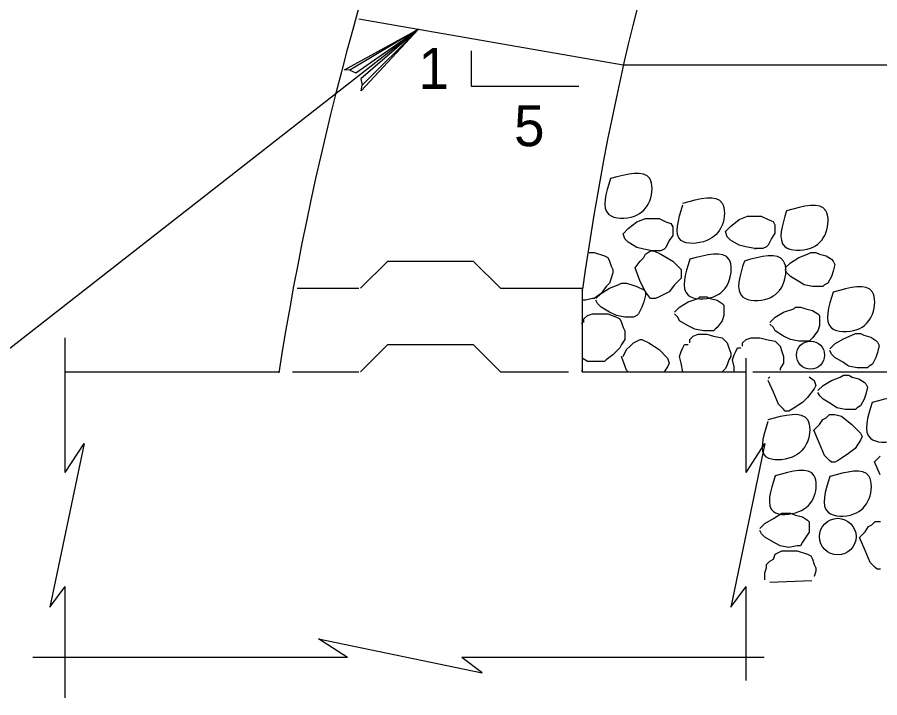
# Model space of a CAD drawing. Extents: x 639028 to 639883, y 298843 to 300031.
# Drawn here: x 639461 to 639524.2, y 299557.3 to 299607.2 of the extents above; entities that cross this region are included whole.
import ezdxf

# ---------------------------------------------------------------- set-up
doc = ezdxf.new("R2010")
doc.units = 0
doc.layers.add('2', color=7, linetype='Continuous')
doc.layers.add('52', color=7, linetype='Continuous')

msp = doc.modelspace()

# ---------------------------------------------------------------- linework, layer by layer
at = {"layer": '2'}
for p, q in [((639485.989, 299607.079), (639505.364, 299603.704)), ((639490.364, 299606.329), (639453.739, 299577.704)), ((639494.245, 299602.124), (639494.245, 299604.732)), ((639505.364, 299603.704), (639538.418, 299603.704)), ((639502.12, 299602.124), (639494.245, 299602.124)), ((639486.114, 299587.329), (639488.114, 299589.329)), ((639488.114, 299589.329), (639494.364, 299589.329)), ((639494.364, 299589.329), (639496.364, 299587.329)), ((639481.489, 299587.329), (639485.989, 299587.329)), ((639496.364, 299587.329), (639502.364, 299587.329)), ((639502.364, 299587.329), (639502.364, 299581.204)), ((639464.489, 299573.829), (639464.489, 299583.704)), ((639486.114, 299581.204), (639488.114, 299583.204)), ((639488.114, 299583.204), (639494.364, 299583.204)), ((639494.364, 299583.204), (639496.364, 299581.204)), ((639514.364, 299573.829), (639514.364, 299582.204)), ((639464.489, 299581.204), (639480.114, 299581.204)), ((639481.128, 299581.204), (639485.989, 299581.204)), ((639496.364, 299581.204), (639501.367, 299581.204)), ((639502.364, 299581.204), (639514.364, 299581.204)), ((639514.864, 299581.204), (639523.364, 299581.204)), ((639515.864, 299581.204), (639532.489, 299581.204)), ((639464.489, 299557.303), (639464.489, 299565.454)), ((639514.364, 299558.566), (639514.364, 299565.454)), ((639485.16, 299560.246), (639462.118, 299560.246)), ((639515.702, 299560.246), (639493.535, 299560.246))]:
    msp.add_line(p, q, dxfattribs=at)
for points in [[(639504.12, 299597.124), (639504.12, 299597.124)], [(639503.739, 299595.329), (639503.739, 299595.329)], [(639513.853, 299592.361), (639514.478, 299592.611)], [(639514.478, 299592.611), (639514.728, 299592.611)], [(639514.728, 299592.611), (639515.103, 299592.611)], [(639515.103, 299592.611), (639515.478, 299592.611)], [(639515.478, 299592.611), (639515.978, 299592.361)], [(639505.739, 299591.704), (639506.364, 299592.204)], [(639506.364, 299592.204), (639506.989, 299592.454)], [(639506.989, 299592.454), (639507.239, 299592.454)], [(639507.239, 299592.454), (639507.614, 299592.454)], [(639507.614, 299592.454), (639507.989, 299592.454)], [(639507.989, 299592.454), (639508.489, 299592.204)], [(639508.489, 299592.204), (639508.864, 299592.079)], [(639508.864, 299592.079), (639508.989, 299591.829)], [(639513.228, 299591.861), (639513.853, 299592.361)], [(639515.978, 299592.361), (639516.353, 299592.236)], [(639516.353, 299592.236), (639516.478, 299591.986)], [(639516.478, 299591.986), (639516.478, 299591.861)], [(639505.364, 299591.329), (639505.739, 299591.704)], [(639505.489, 299590.954), (639505.364, 299591.329)], [(639508.989, 299591.829), (639508.989, 299591.704)], [(639508.989, 299591.704), (639508.989, 299591.204)], [(639512.853, 299591.486), (639513.228, 299591.861)], [(639512.978, 299591.111), (639512.853, 299591.486)], [(639516.478, 299591.361), (639516.228, 299590.986)], [(639516.478, 299591.861), (639516.478, 299591.361)], [(639505.739, 299590.704), (639505.489, 299590.954)], [(639506.364, 299590.329), (639505.739, 299590.704)], [(639508.739, 299590.829), (639508.489, 299590.329)], [(639508.989, 299591.204), (639508.739, 299590.829)], [(639513.228, 299590.861), (639512.978, 299591.111)], [(639513.853, 299590.486), (639513.228, 299590.861)], [(639516.228, 299590.986), (639515.978, 299590.486)], [(639506.864, 299590.204), (639506.364, 299590.329)], [(639507.489, 299590.079), (639506.864, 299590.204)], [(639506.989, 299589.829), (639507.364, 299590.079)], [(639507.364, 299590.079), (639507.489, 299590.079)], [(639507.489, 299590.079), (639507.614, 299590.079)], [(639508.114, 299590.079), (639507.489, 299590.079)], [(639507.614, 299590.079), (639508.114, 299589.829)], [(639508.364, 299590.204), (639508.114, 299590.079)], [(639508.489, 299590.329), (639508.364, 299590.204)], [(639514.353, 299590.361), (639513.853, 299590.486)], [(639514.978, 299590.236), (639514.353, 299590.361)], [(639514.978, 299590.236), (639515.103, 299590.236)], [(639515.603, 299590.236), (639514.978, 299590.236)], [(639515.853, 299590.361), (639515.603, 299590.236)], [(639515.978, 299590.486), (639515.853, 299590.361)], [(639502.864, 299589.954), (639503.239, 299589.954)], [(639503.239, 299589.954), (639503.989, 299589.704)], [(639503.989, 299589.704), (639504.239, 299589.579)], [(639504.239, 299589.579), (639504.364, 299589.329)], [(639506.614, 299589.329), (639506.864, 299589.579)], [(639506.864, 299589.579), (639506.989, 299589.829)], [(639508.114, 299589.829), (639508.989, 299589.329)], [(639517.614, 299589.204), (639518.239, 299589.579)], [(639518.239, 299589.579), (639518.864, 299589.829)], [(639518.864, 299589.829), (639519.114, 299589.954)], [(639519.114, 299589.954), (639519.489, 299589.954)], [(639519.489, 299589.954), (639519.739, 299589.829)], [(639519.739, 299589.829), (639520.239, 299589.704)], [(639520.239, 299589.704), (639520.614, 299589.454)], [(639520.614, 299589.454), (639520.739, 299589.329)], [(639504.364, 299589.329), (639504.489, 299588.954)], [(639504.489, 299588.954), (639504.614, 299588.704)], [(639506.239, 299588.829), (639506.614, 299589.329)], [(639506.614, 299587.829), (639506.239, 299588.829)], [(639508.989, 299589.329), (639509.614, 299588.704)], [(639517.239, 299588.829), (639517.614, 299589.204)], [(639520.739, 299589.329), (639520.864, 299589.079)], [(639520.864, 299589.079), (639520.739, 299588.579)], [(639504.489, 299588.079), (639504.364, 299587.704)], [(639504.614, 299588.454), (639504.489, 299588.079)], [(639504.614, 299588.704), (639504.614, 299588.454)], [(639509.614, 299588.079), (639509.114, 299587.579)], [(639509.614, 299588.704), (639509.614, 299588.454)], [(639509.614, 299588.454), (639509.614, 299588.079)], [(639517.364, 299588.454), (639517.239, 299588.704)], [(639517.614, 299588.204), (639517.364, 299588.454)], [(639518.239, 299587.829), (639517.614, 299588.204)], [(639520.614, 299588.204), (639520.364, 299587.704)], [(639520.739, 299588.579), (639520.614, 299588.204)], [(639504.114, 299587.454), (639503.739, 299586.954)], [(639504.364, 299587.704), (639504.114, 299587.454)], [(639504.364, 299587.329), (639504.989, 299587.579)], [(639504.989, 299587.579), (639505.239, 299587.704)], [(639505.239, 299587.704), (639505.614, 299587.704)], [(639505.614, 299587.704), (639505.989, 299587.579)], [(639505.989, 299587.579), (639506.364, 299587.454)], [(639506.364, 299587.454), (639506.864, 299587.204)], [(639506.989, 299587.079), (639506.614, 299587.829)], [(639509.114, 299587.579), (639508.739, 299587.079)], [(639518.614, 299587.579), (639518.239, 299587.829)], [(639519.239, 299587.454), (639518.614, 299587.579)], [(639519.989, 299587.454), (639519.239, 299587.454)], [(639520.114, 299587.579), (639519.989, 299587.454)], [(639520.364, 299587.704), (639520.114, 299587.579)], [(639503.739, 299586.954), (639503.239, 299586.579)], [(639503.364, 299586.579), (639503.739, 299586.954)], [(639503.739, 299586.954), (639504.364, 299587.329)], [(639506.864, 299587.204), (639506.989, 299587.079)], [(639506.989, 299586.829), (639506.864, 299586.329)], [(639507.364, 299586.579), (639506.989, 299587.079)], [(639506.989, 299587.079), (639506.989, 299586.829)], [(639508.739, 299587.079), (639507.989, 299586.704)], [(639502.614, 299586.454), (639502.364, 299586.454)], [(639503.114, 299586.579), (639502.614, 299586.454)], [(639503.239, 299586.579), (639503.114, 299586.579)], [(639503.489, 299586.204), (639503.364, 299586.454)], [(639503.739, 299585.954), (639503.489, 299586.204)], [(639506.864, 299586.329), (639506.739, 299585.954)], [(639507.489, 299586.579), (639507.364, 299586.579)], [(639507.739, 299586.579), (639507.489, 299586.579)], [(639507.989, 299586.704), (639507.739, 299586.579)], [(639509.489, 299585.954), (639510.114, 299586.329)], [(639510.114, 299586.329), (639510.864, 299586.579)], [(639510.864, 299586.579), (639510.989, 299586.704)], [(639510.989, 299586.704), (639511.489, 299586.704)], [(639511.489, 299586.704), (639511.739, 299586.579)], [(639511.739, 299586.579), (639512.239, 299586.454)], [(639512.239, 299586.454), (639512.614, 299586.204)], [(639512.614, 299586.204), (639512.739, 299586.079)], [(639504.364, 299585.579), (639503.739, 299585.954)], [(639504.864, 299585.329), (639504.364, 299585.579)], [(639506.739, 299585.954), (639506.489, 299585.454)], [(639509.114, 299585.579), (639509.489, 299585.954)], [(639512.739, 299586.079), (639512.739, 299585.829)], [(639512.739, 299585.829), (639512.739, 299585.329)], [(639516.489, 299585.204), (639517.114, 299585.579)], [(639517.114, 299585.579), (639517.864, 299585.829)], [(639517.864, 299585.829), (639517.989, 299585.954)], [(639517.989, 299585.954), (639518.364, 299585.954)], [(639518.364, 299585.954), (639518.739, 299585.829)], [(639518.739, 299585.829), (639519.239, 299585.704)], [(639519.239, 299585.704), (639519.614, 299585.454)], [(639502.489, 299585.079), (639502.739, 299585.329)], [(639502.489, 299584.829), (639502.489, 299585.079)], [(639502.739, 299585.329), (639503.114, 299585.454)], [(639503.114, 299585.454), (639503.739, 299585.454)], [(639503.739, 299585.454), (639504.239, 299585.454)], [(639504.239, 299585.454), (639504.864, 299585.204)], [(639505.489, 299585.204), (639504.864, 299585.329)], [(639504.864, 299585.204), (639505.114, 299585.079)], [(639505.114, 299585.079), (639505.239, 299584.829)], [(639506.114, 299585.204), (639505.489, 299585.204)], [(639506.364, 299585.329), (639506.114, 299585.204)], [(639506.489, 299585.454), (639506.364, 299585.329)], [(639509.364, 299585.204), (639509.114, 299585.454)], [(639509.489, 299584.954), (639509.364, 299585.204)], [(639510.114, 299584.579), (639509.489, 299584.954)], [(639512.614, 299584.954), (639512.239, 299584.454)], [(639512.739, 299585.329), (639512.614, 299584.954)], [(639516.114, 299584.829), (639516.489, 299585.204)], [(639519.614, 299585.454), (639519.739, 299585.329)], [(639519.739, 299585.329), (639519.739, 299585.079)], [(639519.739, 299585.079), (639519.739, 299584.579)], [(639502.364, 299584.704), (639502.364, 299584.829)], [(639505.239, 299584.829), (639505.364, 299584.454)], [(639505.364, 299584.454), (639505.489, 299584.204)], [(639510.614, 299584.329), (639510.114, 299584.579)], [(639511.239, 299584.204), (639510.614, 299584.329)], [(639512.114, 299584.329), (639511.989, 299584.204)], [(639512.239, 299584.454), (639512.114, 299584.329)], [(639516.364, 299584.454), (639516.114, 299584.704)], [(639516.489, 299584.204), (639516.364, 299584.454)], [(639519.739, 299584.579), (639519.614, 299584.204)], [(639505.489, 299584.204), (639505.489, 299583.954)], [(639505.489, 299583.954), (639505.489, 299583.579)], [(639510.239, 299583.579), (639510.489, 299583.829)], [(639510.489, 299583.829), (639510.864, 299583.954)], [(639510.864, 299583.954), (639511.489, 299583.954)], [(639511.989, 299584.204), (639511.239, 299584.204)], [(639511.489, 299583.954), (639511.989, 299583.829)], [(639511.989, 299583.829), (639512.614, 299583.704)], [(639512.614, 299583.704), (639512.864, 299583.454)], [(639514.364, 299583.579), (639514.739, 299583.704)], [(639514.739, 299583.704), (639515.364, 299583.704)], [(639515.364, 299583.704), (639515.864, 299583.579)], [(639517.114, 299583.829), (639516.489, 299584.204)], [(639517.614, 299583.579), (639517.114, 299583.829)], [(639519.239, 299583.704), (639519.114, 299583.579)], [(639519.614, 299584.204), (639519.239, 299583.704)], [(639521.501, 299583.63), (639522.126, 299583.88)], [(639522.126, 299583.88), (639522.376, 299584.005)], [(639522.376, 299584.005), (639522.751, 299584.005)], [(639522.751, 299584.005), (639523.001, 299583.88)], [(639523.001, 299583.88), (639523.501, 299583.755)], [(639523.501, 299583.755), (639523.876, 299583.505)], [(639505.239, 299583.204), (639505.114, 299582.954)], [(639505.489, 299583.579), (639505.239, 299583.204)], [(639505.614, 299582.829), (639505.864, 299583.079)], [(639505.864, 299583.079), (639506.114, 299583.329)], [(639506.114, 299583.329), (639506.364, 299583.454)], [(639506.364, 299583.454), (639506.614, 299583.579)], [(639506.614, 299583.579), (639506.739, 299583.579)], [(639506.739, 299583.579), (639507.239, 299583.329)], [(639507.239, 299583.329), (639507.989, 299582.829)], [(639509.739, 299582.954), (639509.864, 299583.204)], [(639509.864, 299583.204), (639510.114, 299583.204)], [(639510.239, 299583.329), (639510.239, 299583.579)], [(639512.864, 299583.454), (639512.989, 299583.329)], [(639512.989, 299583.329), (639513.114, 299582.954)], [(639514.114, 299583.329), (639514.364, 299583.579)], [(639514.114, 299583.079), (639514.114, 299583.329)], [(639515.864, 299583.579), (639516.489, 299583.454)], [(639516.489, 299583.454), (639516.739, 299583.204)], [(639516.739, 299583.204), (639516.864, 299583.079)], [(639516.864, 299583.079), (639516.989, 299582.704)], [(639518.239, 299583.454), (639517.614, 299583.579)], [(639518.989, 299583.454), (639518.239, 299583.454)], [(639519.114, 299583.579), (639518.989, 299583.454)], [(639520.501, 299582.88), (639520.876, 299583.255)], [(639520.876, 299583.255), (639521.501, 299583.63)], [(639523.876, 299583.505), (639524.001, 299583.38)], [(639524.001, 299583.38), (639524.126, 299583.13)], [(639524.126, 299583.13), (639524.001, 299582.63)], [(639504.614, 299582.454), (639504.114, 299582.079)], [(639505.114, 299582.954), (639504.614, 299582.454)], [(639505.364, 299582.329), (639505.614, 299582.829)], [(639507.989, 299582.829), (639508.614, 299582.204)], [(639509.489, 299582.329), (639509.614, 299582.704)], [(639509.614, 299582.704), (639509.739, 299582.954)], [(639513.114, 299582.954), (639513.239, 299582.579)], [(639513.239, 299582.579), (639513.239, 299582.329)], [(639513.364, 299582.079), (639513.489, 299582.454)], [(639513.489, 299582.454), (639513.614, 299582.704)], [(639513.614, 299582.704), (639513.739, 299582.954)], [(639513.739, 299582.954), (639513.989, 299582.954)], [(639516.989, 299582.704), (639517.114, 299582.329)], [(639520.626, 299582.505), (639520.501, 299582.755)], [(639520.876, 299582.255), (639520.626, 299582.505)], [(639524.001, 299582.63), (639523.876, 299582.255)], [(639502.739, 299581.954), (639502.364, 299582.204), (639502.364, 299582.204)], [(639503.239, 299581.954), (639502.739, 299581.954)], [(639503.614, 299581.954), (639503.239, 299581.954)], [(639503.989, 299581.954), (639503.614, 299581.954)], [(639504.114, 299582.079), (639503.989, 299581.954)], [(639505.614, 299581.329), (639505.239, 299582.329)], [(639508.614, 299582.204), (639508.739, 299581.829)], [(639508.739, 299581.829), (639508.614, 299581.579)], [(639509.614, 299581.829), (639509.489, 299582.329)], [(639509.739, 299581.204), (639509.614, 299581.829)], [(639513.114, 299582.079), (639512.989, 299581.704)], [(639513.239, 299582.329), (639513.114, 299582.079)], [(639513.489, 299581.579), (639513.364, 299582.079)], [(639517.114, 299581.829), (639516.864, 299581.454)], [(639517.114, 299582.329), (639517.114, 299582.079)], [(639517.114, 299582.079), (639517.114, 299581.829)], [(639521.501, 299581.88), (639520.876, 299582.255)], [(639521.876, 299581.63), (639521.501, 299581.88)], [(639523.876, 299582.255), (639523.626, 299581.755)], [(639502.364, 299581.204), (639502.364, 299581.329)], [(639505.739, 299581.204), (639505.614, 299581.329)], [(639505.614, 299581.204), (639505.614, 299581.204)], [(639508.614, 299581.579), (639508.364, 299581.204)], [(639512.864, 299581.454), (639512.614, 299581.204)], [(639512.989, 299581.704), (639512.864, 299581.454)], [(639513.489, 299581.204), (639513.489, 299581.579)], [(639516.864, 299581.454), (639516.864, 299581.329)], [(639522.501, 299581.505), (639521.876, 299581.63)], [(639523.251, 299581.505), (639522.501, 299581.505)], [(639523.376, 299581.63), (639523.251, 299581.505)], [(639523.626, 299581.755), (639523.376, 299581.63)], [(639515.989, 299580.704), (639516.114, 299580.829)], [(639516.364, 299579.704), (639515.989, 299580.579)], [(639518.989, 299580.829), (639519.364, 299580.579)], [(639519.364, 299580.579), (639519.489, 299580.204)], [(639520.009, 299580.198), (639520.634, 299580.573)], [(639520.634, 299580.573), (639521.259, 299580.823)], [(639521.259, 299580.823), (639521.509, 299580.948)], [(639521.509, 299580.948), (639521.884, 299580.948)], [(639521.884, 299580.948), (639522.134, 299580.823)], [(639522.134, 299580.823), (639522.634, 299580.698)], [(639522.634, 299580.698), (639523.009, 299580.448)], [(639519.364, 299579.954), (639518.864, 299579.329)], [(639519.489, 299580.204), (639519.364, 299579.954)], [(639519.634, 299579.823), (639520.009, 299580.198)], [(639523.009, 299580.448), (639523.134, 299580.323)], [(639523.134, 299580.323), (639523.259, 299580.073)], [(639523.259, 299580.073), (639523.134, 299579.573)], [(639516.739, 299578.829), (639516.364, 299579.704)], [(639518.864, 299579.329), (639518.489, 299578.954)], [(639519.759, 299579.448), (639519.634, 299579.698)], [(639520.009, 299579.198), (639519.759, 299579.448)], [(639523.134, 299579.573), (639523.009, 299579.198)], [(639517.114, 299578.454), (639516.739, 299578.829)], [(639518.489, 299578.954), (639517.739, 299578.454)], [(639520.634, 299578.823), (639520.009, 299579.198)], [(639521.009, 299578.573), (639520.634, 299578.823)], [(639522.759, 299578.698), (639522.509, 299578.573)], [(639523.009, 299579.198), (639522.759, 299578.698)], [(639517.239, 299578.329), (639517.114, 299578.454)], [(639517.489, 299578.329), (639517.239, 299578.329)], [(639517.739, 299578.454), (639517.489, 299578.329)], [(639520.239, 299577.829), (639520.489, 299578.079)], [(639520.489, 299578.079), (639520.614, 299578.079)], [(639520.614, 299578.079), (639520.864, 299578.079)], [(639520.864, 299578.079), (639521.364, 299577.954)], [(639521.634, 299578.448), (639521.009, 299578.573)], [(639522.384, 299578.448), (639521.634, 299578.448)], [(639522.509, 299578.573), (639522.384, 299578.448)], [(639519.739, 299577.329), (639519.989, 299577.704)], [(639519.989, 299577.704), (639520.239, 299577.829)], [(639521.364, 299577.954), (639522.114, 299577.329)], [(639519.327, 299576.917), (639519.739, 299577.329)], [(639519.739, 299575.954), (639519.327, 299576.917)], [(639522.114, 299577.329), (639522.739, 299576.704)], [(639522.739, 299576.704), (639522.864, 299576.454)], [(639522.739, 299576.204), (639522.364, 299575.579)], [(639522.864, 299576.454), (639522.739, 299576.204)], [(639464.489, 299573.829), (639465.864, 299575.954), (639463.364, 299563.954), (639464.489, 299565.454)], [(639514.364, 299573.829), (639515.739, 299575.954), (639513.239, 299563.954), (639514.364, 299565.454)], [(639520.114, 299575.079), (639519.739, 299575.954)], [(639522.364, 299575.579), (639521.864, 299575.204)], [(639520.489, 299574.704), (639520.114, 299575.079)], [(639521.864, 299575.204), (639521.114, 299574.704)], [(639523.781, 299574.608), (639524.193, 299575.02)], [(639520.614, 299574.579), (639520.489, 299574.704)], [(639520.864, 299574.579), (639520.614, 299574.579)], [(639521.114, 299574.704), (639520.864, 299574.579)], [(639524.193, 299573.645), (639523.781, 299574.608)], [(639515.739, 299570.079), (639516.364, 299570.454)], [(639516.364, 299570.454), (639516.989, 299570.829)], [(639516.989, 299570.829), (639517.239, 299570.829)], [(639517.239, 299570.829), (639517.614, 299570.829)], [(639517.614, 299570.829), (639517.989, 299570.704)], [(639517.989, 299570.704), (639518.489, 299570.579)], [(639518.489, 299570.579), (639518.864, 299570.329)], [(639515.364, 299569.704), (639515.739, 299570.079)], [(639518.864, 299570.329), (639518.989, 299570.204)], [(639518.989, 299570.204), (639518.989, 299569.954)], [(639518.989, 299569.954), (639518.989, 299569.454)], [(639523.085, 299569.479), (639523.335, 299569.854)], [(639523.335, 299569.854), (639523.585, 299569.979)], [(639523.585, 299569.979), (639523.835, 299570.229)], [(639523.835, 299570.229), (639523.96, 299570.229)], [(639523.96, 299570.229), (639524.21, 299570.229)], [(639515.489, 299569.329), (639515.364, 299569.579)], [(639515.739, 299569.079), (639515.489, 299569.329)], [(639518.989, 299569.454), (639518.739, 299569.079)], [(639522.673, 299569.066), (639523.085, 299569.479)], [(639516.364, 299568.704), (639515.739, 299569.079)], [(639516.864, 299568.454), (639516.364, 299568.704)], [(639518.489, 299568.704), (639518.364, 299568.454)], [(639518.739, 299569.079), (639518.489, 299568.704)], [(639522.364, 299568.829), (639522.364, 299568.829)], [(639523.085, 299568.104), (639522.673, 299569.066)], [(639516.489, 299567.829), (639516.739, 299567.954)], [(639516.739, 299567.954), (639516.989, 299568.079)], [(639517.489, 299568.329), (639516.864, 299568.454)], [(639516.989, 299568.079), (639517.614, 299568.079)], [(639518.114, 299568.454), (639517.489, 299568.329)], [(639517.614, 299568.079), (639518.114, 299568.079)], [(639518.364, 299568.454), (639518.114, 299568.454)], [(639518.114, 299568.079), (639518.864, 299567.829)], [(639523.46, 299567.229), (639523.085, 299568.104)], [(639515.864, 299567.079), (639516.114, 299567.329)], [(639516.114, 299567.329), (639516.364, 299567.454)], [(639516.364, 299567.454), (639516.489, 299567.829)], [(639518.864, 299567.829), (639519.114, 299567.704)], [(639519.114, 299567.704), (639519.239, 299567.454)], [(639519.239, 299567.454), (639519.364, 299567.079)], [(639523.835, 299566.854), (639523.46, 299567.229)], [(639515.739, 299566.454), (639515.864, 299566.829)], [(639515.864, 299566.829), (639515.864, 299567.079)], [(639519.364, 299567.079), (639519.489, 299566.829)], [(639519.489, 299566.829), (639519.489, 299566.579)], [(639523.96, 299566.729), (639523.835, 299566.854)], [(639524.21, 299566.729), (639523.96, 299566.729)], [(639515.739, 299565.954), (639515.739, 299566.454)], [(639519.489, 299566.579), (639519.364, 299566.204)], [(639519.364, 299566.204), (639519.364, 299566.204)], [(639515.739, 299565.954), (639515.739, 299565.954)], [(639485.16, 299560.246), (639483.035, 299561.621), (639495.035, 299559.121), (639493.535, 299560.246)]]:
    msp.add_lwpolyline(points, dxfattribs=at)
for centre, radius in [((639519.087, 299582.428), 1.029), ((639521.082, 299569.118), 1.344)]:
    msp.add_circle(centre, radius, dxfattribs=at)
for centre, radius, start, end in [((639705.296, 299545.875), 227.906, 158.14477, 171.1034), ((639695.441, 299560.499), 194.906, 158.88388, 172.10613), ((639705.296, 299545.875), 227.906, 171.08766, 171.1034)]:
    msp.add_arc(centre, radius, start, end, dxfattribs=at)
for points in [[(639504.437, 299595.371), (639507.312, 299595.371), (639507.312, 299593.746), (639506.187, 299592.621), (639504.312, 299592.746), (639504.437, 299595.371)], [(639509.739, 299593.579), (639512.614, 299593.579), (639512.614, 299591.954), (639511.489, 299590.829), (639509.614, 299590.829), (639509.739, 299593.454)], [(639517.337, 299593.017), (639520.212, 299593.017), (639520.212, 299591.392), (639519.087, 299590.267), (639517.212, 299590.392), (639517.337, 299593.017)], [(639510.239, 299589.454), (639513.114, 299589.454), (639513.114, 299587.829), (639511.989, 299586.704), (639510.114, 299586.829), (639510.239, 299589.454)], [(639514.239, 299589.329), (639517.114, 299589.329), (639517.114, 299587.704), (639515.989, 299586.579), (639514.114, 299586.704), (639514.239, 299589.329)], [(639520.748, 299587.054), (639523.623, 299587.054), (639523.623, 299585.429), (639522.498, 299584.304), (639520.623, 299584.429), (639520.748, 299587.054)], [(639523.597, 299578.956), (639526.472, 299578.956), (639526.472, 299577.331), (639525.347, 299576.206), (639523.472, 299576.331), (639523.597, 299578.956)], [(639515.989, 299577.704), (639518.864, 299577.704), (639518.864, 299576.079), (639517.739, 299574.954), (639515.864, 299574.954), (639515.989, 299577.579)], [(639516.489, 299573.579), (639519.364, 299573.579), (639519.364, 299572.079), (639518.239, 299570.954), (639516.364, 299570.954), (639516.489, 299573.579)], [(639520.505, 299573.53), (639523.38, 299573.53), (639523.38, 299571.905), (639522.255, 299570.78), (639520.38, 299570.905), (639520.505, 299573.53)]]:
    msp.add_spline(points, degree=3, dxfattribs=at)
at = {"layer": '52'}
msp.add_line((639516.105, 299565.787), (639519.183, 299565.901), dxfattribs=at)
msp.add_lwpolyline([(639485.346, 299603.332), (639485.775, 299603.134), (639490.364, 299606.329), (639485.346, 299603.332), (639484.955, 299603.349), (639490.364, 299606.329), (639486.138, 299602.676), (639486.233, 299602.224), (639490.364, 299606.329), (639486.157, 299601.812), (639486.233, 299602.224)], dxfattribs=at)

# ---------------------------------------------------------------- texts
at = {"layer": '2'}
for s, p in [('1', (639490.364, 299601.954)), ('5', (639497.37, 299597.749))]:
    msp.add_text(s, height=3, dxfattribs=at).set_placement(p)

doc.saveas('drawing.dxf')
